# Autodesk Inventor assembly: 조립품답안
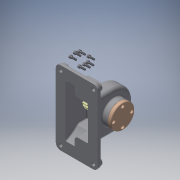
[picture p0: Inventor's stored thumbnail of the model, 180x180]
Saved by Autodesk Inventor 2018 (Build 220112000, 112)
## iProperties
Created: 2024-01
Part Number: 조립품답안
Material: 일반
Document SubType Name: Assembly
Designer: na
Author: na
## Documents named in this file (12)
- C:\Users\na\Desktop\740104V1005\조립품답안.iam
- C:\Users\na\Desktop\740104V1005\본체.ipt
- C:\Users\na\Desktop\740104V1005\깊은 홈 볼 베어링 6202.ipt
- C:\Users\na\Desktop\740104V1005\축.ipt
- C:\Users\na\Desktop\740104V1005\평행 키 5x5x32.ipt
- C:\Users\na\Desktop\740104V1005\평행 키 3x3x12.ipt
- C:\Users\na\Desktop\740104V1005\칼라.ipt
- C:\Users\na\Desktop\740104V1005\스퍼 기어.ipt
- C:\Users\na\Desktop\740104V1005\뒷커버.ipt
- C:\Users\na\Desktop\740104V1005\앞커버.ipt
- C:\Users\na\Desktop\740104V1005\오일 실 15 25 7.ipt
- C:\Users\na\Desktop\740104V1005\육각 소켓 머리 볼트 M4 x 12.ipt
